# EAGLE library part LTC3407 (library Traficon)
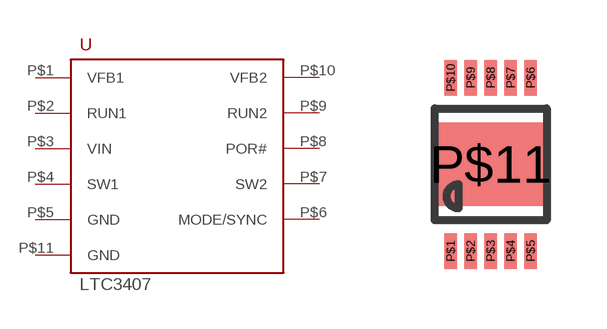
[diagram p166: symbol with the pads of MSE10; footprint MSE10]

Designator prefix U

## LTC3407  [MSE10]
P$1  VFB1
P$2  RUN1
P$3  VIN
P$4  SW1
P$5  GND
P$6  MODE/SYNC
P$7  SW2
P$8  POR#
P$9  RUN2
P$10  VFB2
P$11  GND

## Footprint MSE10 (pad centres in mm)
smd 0.305 x 0.889: P$1 -1,-2.171; P$2 -0.5,-2.171; P$3 0,-2.171; P$4 0.5,-2.171; P$5 1,-2.171; P$6 1,2.171; P$7 0.5,2.171; P$8 0,2.171; P$9 -0.5,2.171; P$10 -1,2.171
smd 2.794 x 2.083: P$11 0,0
